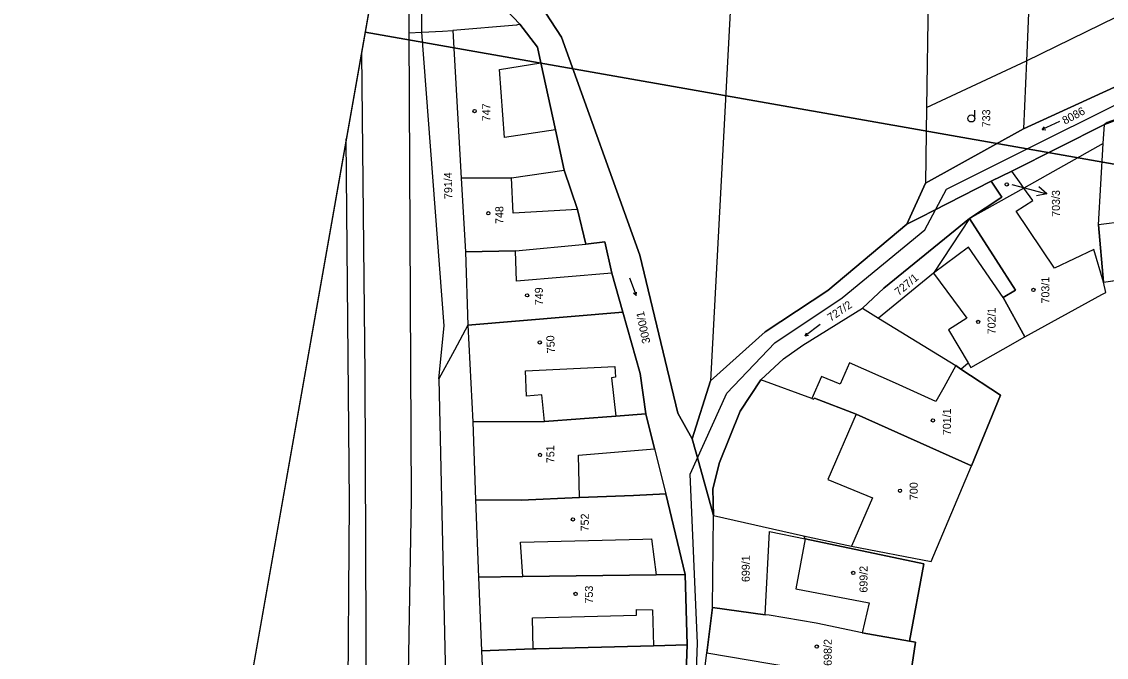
# Model space of a CAD drawing. Extents: x -534481 to -534262, y -1190577 to -1190138.
# Drawn here: x -534480.8 to -534365.7, y -1190410.9 to -1190343.4 of the extents above; entities that cross this region are included whole.
import ezdxf

# ---------------------------------------------------------------- set-up
doc = ezdxf.new("R2010")
doc.units = 0
for name, color, linetype in [('_KN_Město_Hluk', 7, 'Continuous'), ('_KN_Povodí_Moravy', 7, 'Continuous'), ('_N_osa', 7, 'Continuous'), ('_rámeček', 7, 'Continuous'), ('_rámeček_mřížka', 7, 'Continuous'), ('_tenka', 7, 'Continuous'), ('Hranice parcel', 7, 'Continuous'), ('Parcelní čísla', 7, 'Continuous'), ('Polygon budovy', 7, 'Continuous'), ('Pop  PČ popisy', 7, 'Continuous'), ('Značky budov', 7, 'Continuous'), ('Značky kultur', 7, 'Continuous')]:
    doc.layers.add(name, color=color, linetype=linetype)

msp = doc.modelspace()

# ---------------------------------------------------------------- linework, layer by layer
at = {"layer": '_KN_Město_Hluk'}
for p, q in [((-534374.45, -1190354.76), (-534384.87, -1190360.53)), ((-534384.87, -1190360.53), (-534386.83, -1190364.89)), ((-534384.04, -1190363.47), (-534377.88, -1190360.32)), ((-534385.3, -1190364.11), (-534384.04, -1190363.47)), ((-534386.83, -1190364.89), (-534385.3, -1190364.11))]:
    msp.add_line(p, q, dxfattribs=at)
for points in [[(-534354.46, -1190343.91), (-534357.22, -1190346.86), (-534374.45, -1190354.76)], [(-534365.87, -1190354.29), (-534360.78, -1190352.36), (-534359.93, -1190352.28)], [(-534377.88, -1190360.32), (-534375.68, -1190359.24), (-534365.87, -1190354.29)]]:
    msp.add_lwpolyline(points, dxfattribs=at)
at = {"layer": '_KN_Povodí_Moravy'}
for p, q in [((-534425.72, -1190347.72), (-534424.16, -1190354.86)), ((-534424.16, -1190354.86), (-534423.23, -1190359.15)), ((-534423.23, -1190359.15), (-534421.83, -1190363.31)), ((-534377.88, -1190360.32), (-534384.04, -1190363.47)), ((-534376.76, -1190361.99), (-534377.88, -1190360.32)), ((-534380.18, -1190364.29), (-534376.76, -1190361.99)), ((-534421.83, -1190363.31), (-534420.93, -1190367)), ((-534384.04, -1190363.47), (-534385.3, -1190364.11)), ((-534385.3, -1190364.11), (-534386.83, -1190364.89)), ((-534418.19, -1190370.1), (-534417.02, -1190374.22)), ((-534417.02, -1190374.22), (-534415.16, -1190380.76)), ((-534415.16, -1190380.76), (-534414.55, -1190385.03)), ((-534407.69, -1190381.54), (-534409.63, -1190387.68)), ((-534414.55, -1190385.03), (-534413.63, -1190388.75)), ((-534409.63, -1190387.68), (-534409.24, -1190389.07)), ((-534413.63, -1190388.75), (-534412.44, -1190393.55)), ((-534409.24, -1190389.07), (-534408.93, -1190390.19)), ((-534407.36, -1190395.83), (-534408.93, -1190390.19)), ((-534408.93, -1190390.19), (-534407.36, -1190395.83)), ((-534412.44, -1190393.55), (-534410.38, -1190402.1)), ((-534407.5, -1190405.6), (-534407.36, -1190395.83)), ((-534410.38, -1190402.1), (-534410.16, -1190409.59)), ((-534410.16, -1190409.59), (-534410.53, -1190419.49))]:
    msp.add_line(p, q, dxfattribs=at)
for points in [[(-534409.63, -1190387.68), (-534411.18, -1190384.97), (-534415.2, -1190368.18), (-534423.51, -1190345.02), (-534431.92, -1190332.1), (-534432.23, -1190329.13), (-534427.4, -1190310.23), (-534425.49, -1190303.95)], [(-534435.67, -1190327.29), (-534436.59, -1190334.53), (-534427.96, -1190343.61)], [(-534427.96, -1190343.61), (-534426.08, -1190346.07), (-534425.72, -1190347.72)], [(-534391.57, -1190373.81), (-534389.3, -1190371.67), (-534380.18, -1190364.29)], [(-534386.83, -1190364.89), (-534395.25, -1190371.93), (-534401.89, -1190376.32), (-534407.69, -1190381.54)], [(-534420.93, -1190367), (-534418.9, -1190366.76), (-534418.19, -1190370.1)], [(-534402.36, -1190381.41), (-534399.95, -1190379.17), (-534397.88, -1190377.73), (-534391.57, -1190373.81)], [(-534407.36, -1190395.83), (-534407.43, -1190393), (-534406.75, -1190390.22), (-534404.53, -1190384.76), (-534402.36, -1190381.41)], [(-534408.93, -1190390.19), (-534409.24, -1190389.07), (-534409.63, -1190387.68)], [(-534408.57, -1190414.29), (-534408.08, -1190410.44), (-534407.5, -1190405.6)]]:
    msp.add_lwpolyline(points, dxfattribs=at)
at = {"layer": '_N_osa'}
for points in [[(-534409.87, -1190391.44), (-534405.95, -1190382.82), (-534400.87, -1190377.49), (-534393.7, -1190372.72), (-534384.93, -1190365.48), (-534382.63, -1190361.15), (-534355.89, -1190347.82), (-534351.74, -1190342.39), (-534351.58, -1190328.32), (-534347.2, -1190300.92), (-534345.55, -1190283.64), (-534344.68, -1190264.49)], [(-534408.1, -1190518.46), (-534393.62, -1190502.39), (-534391.35, -1190496.96), (-534392.76, -1190488.02), (-534396.65, -1190477.75), (-534402.51, -1190464.28), (-534404.76, -1190456.74), (-534408.31, -1190433.09), (-534409.25, -1190427.88), (-534409.32, -1190416.05), (-534409.08, -1190409.42), (-534409.87, -1190391.44)]]:
    msp.add_lwpolyline(points, dxfattribs=at)
at = {"layer": '_rámeček'}
for points in [[(-534407.91, -1190137.67), (-534480.84, -1190551.29), (-534334.6, -1190577.08), (-534261.67, -1190163.46)], [(-534328.65, -1190258.27), (-534426.15, -1190241.08), (-534444.38, -1190344.48), (-534298.13, -1190370.27)], [(-534298.13, -1190370.27), (-534444.38, -1190344.48), (-534462.61, -1190447.89), (-534316.37, -1190473.68)]]:
    msp.add_lwpolyline(points, dxfattribs=at)
at = {"layer": '_rámeček_mřížka'}
for p, q in [((-534407.91, -1190137.67), (-534480.84, -1190551.29)), ((-534441.42, -1190345), (-534444.38, -1190344.48))]:
    msp.add_line(p, q, dxfattribs=at)
at = {"layer": '_tenka'}
for p, q in [((-534370.65, -1190353.97), (-534372.47, -1190354.82)), ((-534372.47, -1190354.82), (-534372.24, -1190354.53)), ((-534372.47, -1190354.82), (-534372.1, -1190354.84)), ((-534416.28, -1190370.57), (-534415.6, -1190372.46)), ((-534415.6, -1190372.46), (-534415.87, -1190372.21)), ((-534415.6, -1190372.46), (-534415.55, -1190372.09)), ((-534396.05, -1190375.53), (-534397.65, -1190376.74)), ((-534397.65, -1190376.74), (-534397.49, -1190376.41)), ((-534397.65, -1190376.74), (-534397.29, -1190376.68))]:
    msp.add_line(p, q, dxfattribs=at)
at = {"layer": 'Hranice parcel'}
for p, q in [((-534439.78, -1190322.52), (-534439.74, -1190344.56)), ((-534374.14, -1190347.51), (-534353.4, -1190337.34)), ((-534384.58, -1190340.88), (-534384.75, -1190352.48)), ((-534439.74, -1190344.56), (-534438.35, -1190344.48)), ((-534435.05, -1190344.28), (-534434.16, -1190359.98)), ((-534384.75, -1190352.48), (-534374.14, -1190347.51)), ((-534374.14, -1190347.51), (-534374.45, -1190354.76)), ((-534384.75, -1190352.48), (-534384.87, -1190360.53)), ((-534365.99, -1190356.3), (-534365.87, -1190354.29)), ((-534384.87, -1190360.53), (-534374.45, -1190354.76)), ((-534434.16, -1190359.98), (-534433.73, -1190367.83)), ((-534386.83, -1190364.89), (-534384.87, -1190360.53)), ((-534433.73, -1190367.83), (-534433.45, -1190375.62)), ((-534365.97, -1190371.05), (-534357.17, -1190369.75)), ((-534391.57, -1190373.81), (-534389.87, -1190374.86)), ((-534433.45, -1190375.62), (-534417.02, -1190374.22)), ((-534433.45, -1190375.62), (-534432.95, -1190385.88)), ((-534409.63, -1190387.68), (-534407.69, -1190381.54)), ((-534432.95, -1190385.88), (-534432.64, -1190394.16)), ((-534410.38, -1190402.1), (-534412.44, -1190393.55)), ((-534432.64, -1190394.16), (-534432.33, -1190402.39)), ((-534407.5, -1190405.6), (-534407.36, -1190395.83)), ((-534407.36, -1190395.83), (-534397.83, -1190397.99)), ((-534397.83, -1190397.99), (-534397.64, -1190398.3)), ((-534432.33, -1190402.39), (-534432.01, -1190410.21)), ((-534410.16, -1190409.59), (-534410.38, -1190402.1)), ((-534407.5, -1190405.6), (-534401.88, -1190406.38)), ((-534410.53, -1190419.49), (-534410.16, -1190409.59)), ((-534432.01, -1190410.21), (-534431.64, -1190418.94))]:
    msp.add_line(p, q, dxfattribs=at)
for points in [[(-534425.49, -1190303.95), (-534427.4, -1190310.23), (-534432.23, -1190329.13), (-534431.92, -1190332.1), (-534423.51, -1190345.02), (-534415.2, -1190368.18), (-534411.18, -1190384.97), (-534409.63, -1190387.68)], [(-534403.65, -1190306.96), (-534404.41, -1190319.66), (-534407.69, -1190381.54)], [(-534371.05, -1190311.86), (-534373.6, -1190334.76), (-534374.14, -1190347.51)], [(-534438.35, -1190344.48), (-534438.33, -1190339.63), (-534438.5, -1190324.13)], [(-534435.67, -1190327.29), (-534436.59, -1190334.53), (-534427.96, -1190343.61)], [(-534427.96, -1190343.61), (-534428.3, -1190343.74), (-534435.05, -1190344.28)], [(-534423.23, -1190359.15), (-534424.16, -1190354.86), (-534425.72, -1190347.72), (-534426.08, -1190346.07), (-534427.96, -1190343.61)], [(-534374.45, -1190354.76), (-534357.22, -1190346.86), (-534354.46, -1190343.91)], [(-534439.74, -1190344.56), (-534439.47, -1190394.11), (-534439.9, -1190418.87), (-534440.28, -1190422.24), (-534440.49, -1190424.14), (-534441.18, -1190430.2), (-534444.13, -1190442.81), (-534447.66, -1190452.26), (-534455.05, -1190463.52), (-534463.48, -1190473.43), (-534467.83, -1190477.51)], [(-534438.35, -1190344.48), (-534436.15, -1190344.36), (-534435.05, -1190344.28)], [(-534436.55, -1190381.32), (-534435.98, -1190375.67), (-534438.35, -1190344.48)], [(-534444.77, -1190346.72), (-534444.4, -1190380.9), (-534444.21, -1190426.68), (-534448.86, -1190441.43), (-534453.91, -1190451.9), (-534456.83, -1190455.09)], [(-534355.88, -1190351.91), (-534359.93, -1190352.28), (-534360.78, -1190352.36), (-534365.58, -1190354.08), (-534365.87, -1190354.29)], [(-534365.87, -1190354.29), (-534375.68, -1190359.24), (-534377.88, -1190360.32)], [(-534456.83, -1190455.09), (-534453.37, -1190449.76), (-534450.25, -1190441.81), (-534447.54, -1190430.77), (-534446.22, -1190418.57), (-534446.05, -1190394.43), (-534446.37, -1190355.81)], [(-534365.99, -1190356.3), (-534374.41, -1190361.04), (-534380.18, -1190364.29)], [(-534365.97, -1190371.05), (-534366.5, -1190364.95), (-534365.99, -1190356.3)], [(-534434.16, -1190359.98), (-534428.83, -1190359.95), (-534423.23, -1190359.15)], [(-534420.93, -1190367), (-534421.83, -1190363.31), (-534423.23, -1190359.15)], [(-534377.88, -1190360.32), (-534384.04, -1190363.47), (-534385.3, -1190364.11), (-534386.83, -1190364.89)], [(-534377.88, -1190360.32), (-534376.76, -1190361.99), (-534380.18, -1190364.29)], [(-534380.18, -1190364.29), (-534389.3, -1190371.67), (-534391.57, -1190373.81)], [(-534380.18, -1190364.29), (-534384.01, -1190370.07), (-534389.87, -1190374.86)], [(-534374.33, -1190376.84), (-534376.6, -1190372.66), (-534375.29, -1190371.9), (-534377.39, -1190368.63), (-534380.18, -1190364.29)], [(-534407.69, -1190381.54), (-534401.89, -1190376.32), (-534395.25, -1190371.93), (-534386.83, -1190364.89)], [(-534433.73, -1190367.83), (-534428.4, -1190367.72), (-534420.93, -1190367)], [(-534417.02, -1190374.22), (-534418.19, -1190370.1), (-534418.9, -1190366.76), (-534420.93, -1190367)], [(-534374.33, -1190376.84), (-534366.12, -1190372.36), (-534365.7, -1190372.13), (-534365.97, -1190371.05)], [(-534402.36, -1190381.41), (-534399.95, -1190379.17), (-534397.88, -1190377.73), (-534391.57, -1190373.81)], [(-534414.55, -1190385.03), (-534415.16, -1190380.76), (-534417.02, -1190374.22)], [(-534389.87, -1190374.86), (-534381.65, -1190379.91), (-534381.11, -1190380.27)], [(-534433.45, -1190375.62), (-534434.88, -1190378.25), (-534436.55, -1190381.32)], [(-534381.11, -1190380.27), (-534380.34, -1190379.62), (-534380.04, -1190380.12), (-534376.63, -1190378.16), (-534374.33, -1190376.84)], [(-534381.11, -1190380.27), (-534376.9, -1190383.06), (-534379.97, -1190390.57)], [(-534436.55, -1190381.32), (-534435.62, -1190422.59), (-534435.57, -1190424.53), (-534435.47, -1190429), (-534438.93, -1190449.34), (-534449.16, -1190465.21), (-534465.46, -1190480.21), (-534468.81, -1190483.1)], [(-534402.36, -1190381.41), (-534404.53, -1190384.76), (-534406.75, -1190390.22), (-534407.43, -1190393), (-534407.36, -1190395.83)], [(-534379.97, -1190390.57), (-534392.22, -1190385.07), (-534396.64, -1190383.35), (-534396.74, -1190383.48), (-534396.92, -1190383.41), (-534402.36, -1190381.41)], [(-534432.95, -1190385.88), (-534425.33, -1190385.85), (-534417.74, -1190385.27), (-534414.55, -1190385.03)], [(-534414.55, -1190385.03), (-534413.63, -1190388.75), (-534412.44, -1190393.55)], [(-534407.36, -1190395.83), (-534408.93, -1190390.19), (-534409.24, -1190389.07), (-534409.63, -1190387.68)], [(-534397.83, -1190397.99), (-534392.73, -1190399.11), (-534384.27, -1190400.73), (-534379.97, -1190390.57)], [(-534432.64, -1190394.16), (-534427.8, -1190394.2), (-534421.6, -1190393.94), (-534415.89, -1190393.7), (-534412.44, -1190393.55)], [(-534401.88, -1190406.38), (-534401.44, -1190397.52), (-534397.64, -1190398.3)], [(-534397.64, -1190398.3), (-534385.03, -1190400.96), (-534386.57, -1190409.2)], [(-534432.33, -1190402.39), (-534427.61, -1190402.33), (-534413.47, -1190402.14), (-534410.38, -1190402.1)], [(-534408.57, -1190414.29), (-534408.08, -1190410.44), (-534407.5, -1190405.6)], [(-534386.57, -1190409.2), (-534391.59, -1190408.31), (-534396.47, -1190407.28), (-534401.46, -1190406.44), (-534401.88, -1190406.38)], [(-534432.01, -1190410.21), (-534426.52, -1190410), (-534426.22, -1190409.99), (-534413.76, -1190409.68), (-534410.16, -1190409.59)], [(-534386.57, -1190409.2), (-534385.93, -1190409.3), (-534387.24, -1190418.04)]]:
    msp.add_lwpolyline(points, dxfattribs=at)
at = {"layer": 'Polygon budovy'}
for points in [[(-534435.05, -1190344.28), (-534434.16, -1190359.98), (-534428.83, -1190359.95), (-534423.23, -1190359.15), (-534424.16, -1190354.86), (-534429.58, -1190355.65), (-534430.09, -1190348.45), (-534425.72, -1190347.72), (-534426.08, -1190346.07), (-534427.96, -1190343.61), (-534428.3, -1190343.74)], [(-534366.5, -1190364.95), (-534365.97, -1190371.05), (-534357.17, -1190369.75), (-534356.84, -1190364.64), (-534356.15, -1190355.55), (-534355.88, -1190351.91), (-534359.93, -1190352.28), (-534360.28, -1190356.91), (-534360.12, -1190356.93), (-534360.9, -1190364.23)], [(-534434.16, -1190359.98), (-534433.73, -1190367.83), (-534428.4, -1190367.72), (-534420.93, -1190367), (-534421.83, -1190363.31), (-534428.65, -1190363.7), (-534428.83, -1190359.95)], [(-534374.41, -1190361.04), (-534374.71, -1190360.61), (-534375.68, -1190359.24), (-534377.88, -1190360.32), (-534376.76, -1190361.99), (-534380.18, -1190364.29), (-534377.39, -1190368.63), (-534375.29, -1190371.9), (-534376.6, -1190372.66), (-534374.33, -1190376.84), (-534366.12, -1190372.36), (-534365.7, -1190372.13), (-534365.97, -1190371.05), (-534366.99, -1190367.57), (-534371.18, -1190369.54), (-534375.23, -1190363.5), (-534373.47, -1190362.36)], [(-534433.73, -1190367.83), (-534433.45, -1190375.62), (-534417.02, -1190374.22), (-534418.19, -1190370.1), (-534428.28, -1190370.94), (-534428.4, -1190367.72)], [(-534380.29, -1190367.33), (-534384.01, -1190370.07), (-534380.46, -1190374.87), (-534382.43, -1190376.09), (-534380.34, -1190379.62), (-534380.04, -1190380.12), (-534376.63, -1190378.16), (-534374.33, -1190376.84), (-534376.6, -1190372.66)], [(-534433.45, -1190375.62), (-534432.95, -1190385.88), (-534425.33, -1190385.85), (-534425.59, -1190383.03), (-534427.22, -1190383.16), (-534427.35, -1190380.48), (-534417.86, -1190380.01), (-534417.8, -1190381.14), (-534418.2, -1190381.2), (-534417.74, -1190385.27), (-534414.55, -1190385.03), (-534415.16, -1190380.76), (-534417.02, -1190374.22)], [(-534396.92, -1190383.41), (-534396.74, -1190383.48), (-534396.64, -1190383.35), (-534392.22, -1190385.07), (-534379.97, -1190390.57), (-534376.9, -1190383.06), (-534381.11, -1190380.27), (-534381.65, -1190379.91), (-534382.92, -1190382.23), (-534383.75, -1190383.73), (-534388.06, -1190381.79), (-534392.92, -1190379.6), (-534393.92, -1190381.89), (-534395.9, -1190381.05)], [(-534432.95, -1190385.88), (-534432.64, -1190394.16), (-534427.8, -1190394.2), (-534421.6, -1190393.94), (-534421.73, -1190389.42), (-534413.63, -1190388.75), (-534414.55, -1190385.03), (-534417.74, -1190385.27), (-534425.33, -1190385.85)], [(-534392.73, -1190399.11), (-534384.27, -1190400.73), (-534379.97, -1190390.57), (-534392.22, -1190385.07), (-534395.24, -1190392.02), (-534390.48, -1190393.97)], [(-534432.64, -1190394.16), (-534432.33, -1190402.39), (-534427.61, -1190402.33), (-534427.86, -1190398.67), (-534414.87, -1190398.34), (-534413.97, -1190398.32), (-534413.47, -1190402.14), (-534410.38, -1190402.1), (-534412.44, -1190393.55), (-534415.89, -1190393.7), (-534421.6, -1190393.94), (-534427.8, -1190394.2)], [(-534397.64, -1190398.3), (-534398.63, -1190403.64), (-534390.83, -1190405.11), (-534391.59, -1190408.31), (-534386.57, -1190409.2), (-534385.03, -1190400.96)], [(-534410.38, -1190402.1), (-534413.47, -1190402.14), (-534427.61, -1190402.33), (-534432.33, -1190402.39), (-534432.01, -1190410.21), (-534426.52, -1190410), (-534426.6, -1190406.71), (-534415.56, -1190406.44), (-534415.57, -1190405.83), (-534413.87, -1190405.85), (-534413.76, -1190409.68), (-534410.16, -1190409.59)], [(-534407.5, -1190405.6), (-534408.08, -1190410.44), (-534392.41, -1190413.1), (-534392.96, -1190416.94), (-534387.24, -1190418.04), (-534385.93, -1190409.3), (-534386.57, -1190409.2), (-534391.59, -1190408.31), (-534396.47, -1190407.28), (-534401.46, -1190406.44), (-534401.88, -1190406.38)], [(-534432.01, -1190410.21), (-534431.64, -1190418.94), (-534426.32, -1190419.08), (-534426.42, -1190414.81), (-534414.11, -1190414.44), (-534414.2, -1190417.03), (-534415.78, -1190417), (-534415.84, -1190419.35), (-534410.53, -1190419.49), (-534410.16, -1190409.59), (-534413.76, -1190409.68), (-534426.22, -1190409.99), (-534426.52, -1190410)]]:
    msp.add_lwpolyline(points, close=True, dxfattribs=at)
at = {"layer": 'Pop  PČ popisy'}
for p, q in [((-534375.68, -1190360.66), (-534374.87, -1190360.88)), ((-534374.87, -1190360.88), (-534371.97, -1190361.66)), ((-534371.97, -1190361.66), (-534372.81, -1190360.91)), ((-534371.97, -1190361.66), (-534373.07, -1190361.88))]:
    msp.add_line(p, q, dxfattribs=at)
at = {"layer": 'Značky budov'}
for centre in [(-534432.75, -1190352.86), (-534376.24, -1190360.66), (-534431.29, -1190363.72), (-534373.4, -1190371.86), (-534427.18, -1190372.44), (-534379.27, -1190375.26), (-534425.83, -1190377.45), (-534384.07, -1190385.73), (-534425.8, -1190389.4), (-534387.57, -1190393.21), (-534422.31, -1190396.26), (-534392.54, -1190401.94), (-534422.02, -1190404.17), (-534396.41, -1190409.77)]:
    msp.add_circle(centre, 0.175, dxfattribs=at)
at = {"layer": 'Značky kultur'}
msp.add_line((-534379.62, -1190353.64), (-534379.62, -1190352.77), dxfattribs=at)
msp.add_circle((-534380, -1190353.64), 0.375, dxfattribs=at)

# ---------------------------------------------------------------- texts
at = {"layer": '_tenka'}
for s, rotation, p in [('8086', 27.9902, (-534370.06, -1190354.31)), ('727/2', 34.1782, (-534394.93, -1190375.25)), ('3000/1', 101.5337, (-534414.08, -1190377.48))]:
    msp.add_text(s, height=0.85, rotation=rotation, dxfattribs=at).set_placement(p)
at = {"layer": 'Parcelní čísla'}
for s, rotation, p in [('747', 90, (-534431.08, -1190353.95)), ('733', 90, (-534377.99, -1190354.58)), ('791/4', 91, (-534435.11, -1190362.2)), ('703/3', 90, (-534370.59, -1190364.1)), ('748', 90, (-534429.69, -1190364.86)), ('727/1', 40, (-534387.71, -1190372.53)), ('703/1', 90, (-534371.71, -1190373.31)), ('749', 90, (-534425.5, -1190373.49)), ('702/1', 90, (-534377.42, -1190376.58)), ('750', 93, (-534424.2, -1190378.57)), ('701/1', 90, (-534382.17, -1190387.3)), ('751', 91, (-534424.26, -1190390.27)), ('700', 90, (-534385.69, -1190394.2)), ('752', 90, (-534420.62, -1190397.52)), ('699/1', 90, (-534403.53, -1190402.91)), ('699/2', 90, (-534391.02, -1190404.03)), ('753', 90, (-534420.18, -1190405.19)), ('698/2', 90, (-534394.82, -1190411.81))]:
    msp.add_text(s, height=0.85, rotation=rotation, dxfattribs=at).set_placement(p)

doc.saveas('drawing.dxf')
